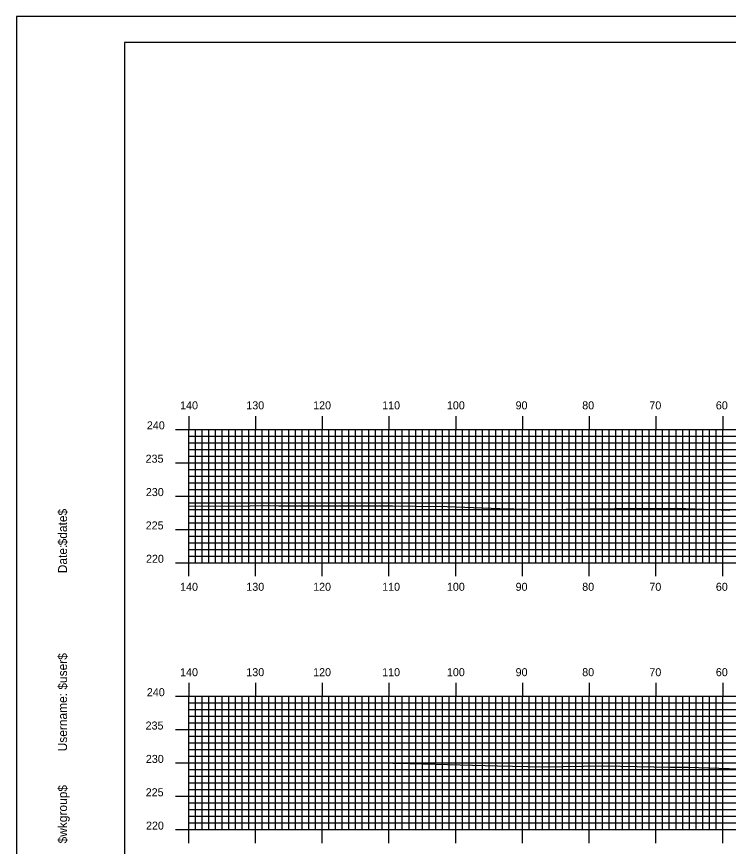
# Model space of a CAD drawing. Extents: x 1803503 to 1803847, y 442591 to 442811.
# Drawn here: x 1803503.4 to 1803610, y 442686.2 to 442810.5 of the extents above; entities that cross this region are included whole.
import ezdxf

# ---------------------------------------------------------------- set-up
doc = ezdxf.new("R2010")
doc.units = 0
for name, color, linetype in [('BORDER', 7, 'Continuous'), ('H_V ANNOTATION', 7, 'Continuous'), ('MAJOR', 7, 'Continuous'), ('MINOR', 7, 'Continuous'), ('PLOT BOUNDARY', 7, 'Continuous'), ('S_Roadway_Centerline', 7, 'Continuous')]:
    doc.layers.add(name, color=color, linetype=linetype)

msp = doc.modelspace()

# ---------------------------------------------------------------- linework, layer by layer
at = {"layer": 'BORDER'}
msp.add_lwpolyline([(1803519.54, 442596.67), (1803839.54, 442596.67), (1803839.54, 442806.67), (1803519.54, 442806.67)], close=True, dxfattribs=at)
at = {"layer": 'MAJOR'}
for p, q in [((1803529.14, 442750.67), (1803529.14, 442748.67)), ((1803539.14, 442750.67), (1803539.14, 442748.67)), ((1803549.14, 442750.67), (1803549.14, 442748.67)), ((1803559.14, 442750.67), (1803559.14, 442748.67)), ((1803569.14, 442750.67), (1803569.14, 442748.67)), ((1803579.14, 442750.67), (1803579.14, 442748.67)), ((1803589.14, 442750.67), (1803589.14, 442748.67)), ((1803599.14, 442750.67), (1803599.14, 442748.67)), ((1803609.14, 442750.67), (1803609.14, 442748.67)), ((1803527.14, 442748.67), (1803529.14, 442748.67)), ((1803529.14, 442748.67), (1803809.14, 442748.67)), ((1803529.14, 442728.67), (1803529.14, 442748.67)), ((1803529.14, 442728.67), (1803529.14, 442748.67)), ((1803529.14, 442748.67), (1803809.14, 442748.67)), ((1803539.14, 442728.67), (1803539.14, 442748.67)), ((1803549.14, 442728.67), (1803549.14, 442748.67)), ((1803559.14, 442728.67), (1803559.14, 442748.67)), ((1803569.14, 442728.67), (1803569.14, 442748.67)), ((1803579.14, 442728.67), (1803579.14, 442748.67)), ((1803589.14, 442728.67), (1803589.14, 442748.67)), ((1803599.14, 442728.67), (1803599.14, 442748.67)), ((1803609.14, 442728.67), (1803609.14, 442748.67)), ((1803527.14, 442743.67), (1803529.14, 442743.67)), ((1803529.14, 442743.67), (1803809.14, 442743.67)), ((1803527.14, 442738.67), (1803529.14, 442738.67)), ((1803529.14, 442738.67), (1803809.14, 442738.67)), ((1803527.14, 442733.67), (1803529.14, 442733.67)), ((1803529.14, 442733.67), (1803809.14, 442733.67)), ((1803527.14, 442728.67), (1803529.14, 442728.67)), ((1803529.14, 442728.67), (1803809.14, 442728.67)), ((1803529.14, 442728.67), (1803809.14, 442728.67)), ((1803529.14, 442726.66), (1803529.14, 442728.67)), ((1803539.14, 442726.66), (1803539.14, 442728.67)), ((1803549.14, 442726.66), (1803549.14, 442728.67)), ((1803559.14, 442726.66), (1803559.14, 442728.67)), ((1803569.14, 442726.66), (1803569.14, 442728.67)), ((1803579.14, 442726.66), (1803579.14, 442728.67)), ((1803589.14, 442726.66), (1803589.14, 442728.67)), ((1803599.14, 442726.66), (1803599.14, 442728.67)), ((1803609.14, 442726.66), (1803609.14, 442728.67)), ((1803529.14, 442710.67), (1803529.14, 442708.67)), ((1803539.14, 442710.67), (1803539.14, 442708.67)), ((1803549.14, 442710.67), (1803549.14, 442708.67)), ((1803559.14, 442710.67), (1803559.14, 442708.67)), ((1803569.14, 442710.67), (1803569.14, 442708.67)), ((1803579.14, 442710.67), (1803579.14, 442708.67)), ((1803589.14, 442710.67), (1803589.14, 442708.67)), ((1803599.14, 442710.67), (1803599.14, 442708.67)), ((1803609.14, 442710.67), (1803609.14, 442708.67)), ((1803527.14, 442708.67), (1803529.14, 442708.67)), ((1803529.14, 442708.67), (1803809.14, 442708.67)), ((1803529.14, 442688.67), (1803529.14, 442708.67)), ((1803529.14, 442688.67), (1803529.14, 442708.67)), ((1803529.14, 442708.67), (1803809.14, 442708.67)), ((1803539.14, 442688.67), (1803539.14, 442708.67)), ((1803549.14, 442688.67), (1803549.14, 442708.67)), ((1803559.14, 442688.67), (1803559.14, 442708.67)), ((1803569.14, 442688.67), (1803569.14, 442708.67)), ((1803579.14, 442688.67), (1803579.14, 442708.67)), ((1803589.14, 442688.67), (1803589.14, 442708.67)), ((1803599.14, 442688.67), (1803599.14, 442708.67)), ((1803609.14, 442688.67), (1803609.14, 442708.67)), ((1803527.14, 442703.67), (1803529.14, 442703.67)), ((1803529.14, 442703.67), (1803809.14, 442703.67)), ((1803527.14, 442698.67), (1803529.14, 442698.67)), ((1803529.14, 442698.67), (1803809.14, 442698.67)), ((1803527.14, 442693.67), (1803529.14, 442693.67)), ((1803529.14, 442693.67), (1803809.14, 442693.67)), ((1803527.14, 442688.67), (1803529.14, 442688.67)), ((1803529.14, 442688.67), (1803809.14, 442688.67)), ((1803529.14, 442688.67), (1803809.14, 442688.67)), ((1803529.14, 442686.66), (1803529.14, 442688.67)), ((1803539.14, 442686.66), (1803539.14, 442688.67)), ((1803549.14, 442686.66), (1803549.14, 442688.67)), ((1803559.14, 442686.66), (1803559.14, 442688.67)), ((1803569.14, 442686.66), (1803569.14, 442688.67)), ((1803579.14, 442686.66), (1803579.14, 442688.67)), ((1803589.14, 442686.66), (1803589.14, 442688.67)), ((1803599.14, 442686.66), (1803599.14, 442688.67)), ((1803609.14, 442686.66), (1803609.14, 442688.67))]:
    msp.add_line(p, q, dxfattribs=at)
at = {"layer": 'MINOR'}
for p, q in [((1803530.14, 442728.67), (1803530.14, 442748.67)), ((1803531.14, 442728.67), (1803531.14, 442748.67)), ((1803532.14, 442728.67), (1803532.14, 442748.67)), ((1803533.14, 442728.67), (1803533.14, 442748.67)), ((1803534.14, 442728.67), (1803534.14, 442748.67)), ((1803535.14, 442728.67), (1803535.14, 442748.67)), ((1803536.14, 442728.67), (1803536.14, 442748.67)), ((1803537.14, 442728.67), (1803537.14, 442748.67)), ((1803538.14, 442728.67), (1803538.14, 442748.67)), ((1803540.14, 442728.67), (1803540.14, 442748.67)), ((1803541.14, 442728.67), (1803541.14, 442748.67)), ((1803542.14, 442728.67), (1803542.14, 442748.67)), ((1803543.14, 442728.67), (1803543.14, 442748.67)), ((1803544.14, 442728.67), (1803544.14, 442748.67)), ((1803545.14, 442728.67), (1803545.14, 442748.67)), ((1803546.14, 442728.67), (1803546.14, 442748.67)), ((1803547.14, 442728.67), (1803547.14, 442748.67)), ((1803548.14, 442728.67), (1803548.14, 442748.67)), ((1803550.14, 442728.67), (1803550.14, 442748.67)), ((1803551.14, 442728.67), (1803551.14, 442748.67)), ((1803552.14, 442728.67), (1803552.14, 442748.67)), ((1803553.14, 442728.67), (1803553.14, 442748.67)), ((1803554.14, 442728.67), (1803554.14, 442748.67)), ((1803555.14, 442728.67), (1803555.14, 442748.67)), ((1803556.14, 442728.67), (1803556.14, 442748.67)), ((1803557.14, 442728.67), (1803557.14, 442748.67)), ((1803558.14, 442728.67), (1803558.14, 442748.67)), ((1803560.14, 442728.67), (1803560.14, 442748.67)), ((1803561.14, 442728.67), (1803561.14, 442748.67)), ((1803562.14, 442728.67), (1803562.14, 442748.67)), ((1803563.14, 442728.67), (1803563.14, 442748.67)), ((1803564.14, 442728.67), (1803564.14, 442748.67)), ((1803565.14, 442728.67), (1803565.14, 442748.67)), ((1803566.14, 442728.67), (1803566.14, 442748.67)), ((1803567.14, 442728.67), (1803567.14, 442748.67)), ((1803568.14, 442728.67), (1803568.14, 442748.67)), ((1803570.14, 442728.67), (1803570.14, 442748.67)), ((1803571.14, 442728.67), (1803571.14, 442748.67)), ((1803572.14, 442728.67), (1803572.14, 442748.67)), ((1803573.14, 442728.67), (1803573.14, 442748.67)), ((1803574.14, 442728.67), (1803574.14, 442748.67)), ((1803575.14, 442728.67), (1803575.14, 442748.67)), ((1803576.14, 442728.67), (1803576.14, 442748.67)), ((1803577.14, 442728.67), (1803577.14, 442748.67)), ((1803578.14, 442728.67), (1803578.14, 442748.67)), ((1803580.14, 442728.67), (1803580.14, 442748.67)), ((1803581.14, 442728.67), (1803581.14, 442748.67)), ((1803582.14, 442728.67), (1803582.14, 442748.67)), ((1803583.14, 442728.67), (1803583.14, 442748.67)), ((1803584.14, 442728.67), (1803584.14, 442748.67)), ((1803585.14, 442728.67), (1803585.14, 442748.67)), ((1803586.14, 442728.67), (1803586.14, 442748.67)), ((1803587.14, 442728.67), (1803587.14, 442748.67)), ((1803588.14, 442728.67), (1803588.14, 442748.67)), ((1803590.14, 442728.67), (1803590.14, 442748.67)), ((1803591.14, 442728.67), (1803591.14, 442748.67)), ((1803592.14, 442728.67), (1803592.14, 442748.67)), ((1803593.14, 442728.67), (1803593.14, 442748.67)), ((1803594.14, 442728.67), (1803594.14, 442748.67)), ((1803595.14, 442728.67), (1803595.14, 442748.67)), ((1803596.14, 442728.67), (1803596.14, 442748.67)), ((1803597.14, 442728.67), (1803597.14, 442748.67)), ((1803598.14, 442728.67), (1803598.14, 442748.67)), ((1803600.14, 442728.67), (1803600.14, 442748.67)), ((1803601.14, 442728.67), (1803601.14, 442748.67)), ((1803602.14, 442728.67), (1803602.14, 442748.67)), ((1803603.14, 442728.67), (1803603.14, 442748.67)), ((1803604.14, 442728.67), (1803604.14, 442748.67)), ((1803605.14, 442728.67), (1803605.14, 442748.67)), ((1803606.14, 442728.67), (1803606.14, 442748.67)), ((1803607.14, 442728.67), (1803607.14, 442748.67)), ((1803608.14, 442728.67), (1803608.14, 442748.67)), ((1803529.14, 442747.67), (1803809.14, 442747.67)), ((1803529.14, 442747.67), (1803531.14, 442747.67)), ((1803529.14, 442746.67), (1803809.14, 442746.67)), ((1803529.14, 442746.67), (1803531.14, 442746.67)), ((1803529.14, 442745.67), (1803809.14, 442745.67)), ((1803529.14, 442745.67), (1803531.14, 442745.67)), ((1803529.14, 442744.67), (1803809.14, 442744.67)), ((1803529.14, 442744.67), (1803531.14, 442744.67)), ((1803529.14, 442742.67), (1803809.14, 442742.67)), ((1803529.14, 442742.67), (1803531.14, 442742.67)), ((1803529.14, 442741.67), (1803809.14, 442741.67)), ((1803529.14, 442741.67), (1803531.14, 442741.67)), ((1803529.14, 442740.67), (1803809.14, 442740.67)), ((1803529.14, 442740.67), (1803531.14, 442740.67)), ((1803529.14, 442739.67), (1803809.14, 442739.67)), ((1803529.14, 442739.67), (1803531.14, 442739.67)), ((1803529.14, 442737.67), (1803809.14, 442737.67)), ((1803529.14, 442737.67), (1803531.14, 442737.67)), ((1803529.14, 442736.67), (1803809.14, 442736.67)), ((1803529.14, 442736.67), (1803531.14, 442736.67)), ((1803529.14, 442735.67), (1803809.14, 442735.67)), ((1803529.14, 442735.67), (1803531.14, 442735.67)), ((1803529.14, 442734.67), (1803809.14, 442734.67)), ((1803529.14, 442734.67), (1803531.14, 442734.67)), ((1803529.14, 442732.67), (1803809.14, 442732.67)), ((1803529.14, 442732.67), (1803531.14, 442732.67)), ((1803529.14, 442731.67), (1803809.14, 442731.67)), ((1803529.14, 442731.67), (1803531.14, 442731.67)), ((1803529.14, 442730.67), (1803809.14, 442730.67)), ((1803529.14, 442730.67), (1803531.14, 442730.67)), ((1803529.14, 442729.67), (1803809.14, 442729.67)), ((1803529.14, 442729.67), (1803531.14, 442729.67)), ((1803530.14, 442688.67), (1803530.14, 442708.67)), ((1803531.14, 442688.67), (1803531.14, 442708.67)), ((1803532.14, 442688.67), (1803532.14, 442708.67)), ((1803533.14, 442688.67), (1803533.14, 442708.67)), ((1803534.14, 442688.67), (1803534.14, 442708.67)), ((1803535.14, 442688.67), (1803535.14, 442708.67)), ((1803536.14, 442688.67), (1803536.14, 442708.67)), ((1803537.14, 442688.67), (1803537.14, 442708.67)), ((1803538.14, 442688.67), (1803538.14, 442708.67)), ((1803540.14, 442688.67), (1803540.14, 442708.67)), ((1803541.14, 442688.67), (1803541.14, 442708.67)), ((1803542.14, 442688.67), (1803542.14, 442708.67)), ((1803543.14, 442688.67), (1803543.14, 442708.67)), ((1803544.14, 442688.67), (1803544.14, 442708.67)), ((1803545.14, 442688.67), (1803545.14, 442708.67)), ((1803546.14, 442688.67), (1803546.14, 442708.67)), ((1803547.14, 442688.67), (1803547.14, 442708.67)), ((1803548.14, 442688.67), (1803548.14, 442708.67)), ((1803550.14, 442688.67), (1803550.14, 442708.67)), ((1803551.14, 442688.67), (1803551.14, 442708.67)), ((1803552.14, 442688.67), (1803552.14, 442708.67)), ((1803553.14, 442688.67), (1803553.14, 442708.67)), ((1803554.14, 442688.67), (1803554.14, 442708.67)), ((1803555.14, 442688.67), (1803555.14, 442708.67)), ((1803556.14, 442688.67), (1803556.14, 442708.67)), ((1803557.14, 442688.67), (1803557.14, 442708.67)), ((1803558.14, 442688.67), (1803558.14, 442708.67)), ((1803560.14, 442688.67), (1803560.14, 442708.67)), ((1803561.14, 442688.67), (1803561.14, 442708.67)), ((1803562.14, 442688.67), (1803562.14, 442708.67)), ((1803563.14, 442688.67), (1803563.14, 442708.67)), ((1803564.14, 442688.67), (1803564.14, 442708.67)), ((1803565.14, 442688.67), (1803565.14, 442708.67)), ((1803566.14, 442688.67), (1803566.14, 442708.67)), ((1803567.14, 442688.67), (1803567.14, 442708.67)), ((1803568.14, 442688.67), (1803568.14, 442708.67)), ((1803570.14, 442688.67), (1803570.14, 442708.67)), ((1803571.14, 442688.67), (1803571.14, 442708.67)), ((1803572.14, 442688.67), (1803572.14, 442708.67)), ((1803573.14, 442688.67), (1803573.14, 442708.67)), ((1803574.14, 442688.67), (1803574.14, 442708.67)), ((1803575.14, 442688.67), (1803575.14, 442708.67)), ((1803576.14, 442688.67), (1803576.14, 442708.67)), ((1803577.14, 442688.67), (1803577.14, 442708.67)), ((1803578.14, 442688.67), (1803578.14, 442708.67)), ((1803580.14, 442688.67), (1803580.14, 442708.67)), ((1803581.14, 442688.67), (1803581.14, 442708.67)), ((1803582.14, 442688.67), (1803582.14, 442708.67)), ((1803583.14, 442688.67), (1803583.14, 442708.67)), ((1803584.14, 442688.67), (1803584.14, 442708.67)), ((1803585.14, 442688.67), (1803585.14, 442708.67)), ((1803586.14, 442688.67), (1803586.14, 442708.67)), ((1803587.14, 442688.67), (1803587.14, 442708.67)), ((1803588.14, 442688.67), (1803588.14, 442708.67)), ((1803590.14, 442688.67), (1803590.14, 442708.67)), ((1803591.14, 442688.67), (1803591.14, 442708.67)), ((1803592.14, 442688.67), (1803592.14, 442708.67)), ((1803593.14, 442688.67), (1803593.14, 442708.67)), ((1803594.14, 442688.67), (1803594.14, 442708.67)), ((1803595.14, 442688.67), (1803595.14, 442708.67)), ((1803596.14, 442688.67), (1803596.14, 442708.67)), ((1803597.14, 442688.67), (1803597.14, 442708.67)), ((1803598.14, 442688.67), (1803598.14, 442708.67)), ((1803600.14, 442688.67), (1803600.14, 442708.67)), ((1803601.14, 442688.67), (1803601.14, 442708.67)), ((1803602.14, 442688.67), (1803602.14, 442708.67)), ((1803603.14, 442688.67), (1803603.14, 442708.67)), ((1803604.14, 442688.67), (1803604.14, 442708.67)), ((1803605.14, 442688.67), (1803605.14, 442708.67)), ((1803606.14, 442688.67), (1803606.14, 442708.67)), ((1803607.14, 442688.67), (1803607.14, 442708.67)), ((1803608.14, 442688.67), (1803608.14, 442708.67)), ((1803529.14, 442707.67), (1803809.14, 442707.67)), ((1803529.14, 442707.67), (1803531.14, 442707.67)), ((1803529.14, 442706.67), (1803809.14, 442706.67)), ((1803529.14, 442706.67), (1803531.14, 442706.67)), ((1803529.14, 442705.67), (1803809.14, 442705.67)), ((1803529.14, 442705.67), (1803531.14, 442705.67)), ((1803529.14, 442704.67), (1803809.14, 442704.67)), ((1803529.14, 442704.67), (1803531.14, 442704.67)), ((1803529.14, 442702.67), (1803809.14, 442702.67)), ((1803529.14, 442702.67), (1803531.14, 442702.67)), ((1803529.14, 442701.67), (1803809.14, 442701.67)), ((1803529.14, 442701.67), (1803531.14, 442701.67)), ((1803529.14, 442700.67), (1803809.14, 442700.67)), ((1803529.14, 442700.67), (1803531.14, 442700.67)), ((1803529.14, 442699.67), (1803809.14, 442699.67)), ((1803529.14, 442699.67), (1803531.14, 442699.67)), ((1803529.14, 442697.67), (1803809.14, 442697.67)), ((1803529.14, 442697.67), (1803531.14, 442697.67)), ((1803529.14, 442696.67), (1803809.14, 442696.67)), ((1803529.14, 442696.67), (1803531.14, 442696.67)), ((1803529.14, 442695.67), (1803809.14, 442695.67)), ((1803529.14, 442695.67), (1803531.14, 442695.67)), ((1803529.14, 442694.67), (1803809.14, 442694.67)), ((1803529.14, 442694.67), (1803531.14, 442694.67)), ((1803529.14, 442692.67), (1803809.14, 442692.67)), ((1803529.14, 442692.67), (1803531.14, 442692.67)), ((1803529.14, 442691.67), (1803809.14, 442691.67)), ((1803529.14, 442691.67), (1803531.14, 442691.67)), ((1803529.14, 442690.67), (1803809.14, 442690.67)), ((1803529.14, 442690.67), (1803531.14, 442690.67)), ((1803529.14, 442689.67), (1803809.14, 442689.67)), ((1803529.14, 442689.67), (1803531.14, 442689.67))]:
    msp.add_line(p, q, dxfattribs=at)
at = {"layer": 'PLOT BOUNDARY'}
msp.add_lwpolyline([(1803503.35, 442590.55), (1803843.35, 442590.55), (1803843.35, 442810.55), (1803503.35, 442810.55)], close=True, dxfattribs=at)
at = {"layer": 'S_Roadway_Centerline'}
for points in [[(1803529.14, 442737.18), (1803538.35, 442737.21), (1803540.31, 442737.27), (1803542.6, 442737.22), (1803552.62, 442737.22), (1803559.65, 442737.22), (1803563.19, 442737.17), (1803567.87, 442737.11), (1803575.74, 442736.83), (1803581.97, 442736.67), (1803592.91, 442736.82), (1803602.33, 442736.84), (1803610.21, 442736.54)], [(1803529.14, 442698.69), (1803541.02, 442698.65), (1803544.17, 442698.66), (1803548.96, 442698.7), (1803557.09, 442698.68), (1803562.32, 442698.58), (1803575.38, 442698.23), (1803582.17, 442698.09), (1803591.35, 442698.24), (1803601.34, 442698.03), (1803602.78, 442698.04), (1803603.95, 442698.02), (1803617.75, 442697.56)]]:
    msp.add_lwpolyline(points, dxfattribs=at)

# ---------------------------------------------------------------- texts
at = {"layer": 'BORDER'}
for s, p in [('$date$', (1803510.91, 442731.28)), ('Date:', (1803510.91, 442727.1)), ('$user$', (1803510.91, 442709.65)), ('Username:', (1803510.91, 442700.4)), ('$wkgroup$', (1803510.91, 442686.6))]:
    msp.add_text(s, height=1.339, rotation=90, dxfattribs=at).set_placement(p)
at = {"layer": 'H_V ANNOTATION'}
for s, p in [('140', (1803527.85, 442751.67)), ('130', (1803537.77, 442751.67)), ('120', (1803547.78, 442751.67)), ('110', (1803558.12, 442751.67)), ('100', (1803567.82, 442751.67)), ('90', (1803578.11, 442751.67)), ('80', (1803588.09, 442751.67)), ('70', (1803598.15, 442751.67)), ('60', (1803608.11, 442751.67)), ('240', (1803522.87, 442748.67)), ('235', (1803522.68, 442743.67)), ('230', (1803522.72, 442738.67)), ('225', (1803522.7, 442733.67)), ('220', (1803522.74, 442728.67)), ('140', (1803527.85, 442724.47)), ('130', (1803537.77, 442724.47)), ('120', (1803547.78, 442724.47)), ('110', (1803558.12, 442724.47)), ('100', (1803567.82, 442724.47)), ('90', (1803578.11, 442724.47)), ('80', (1803588.09, 442724.47)), ('70', (1803598.15, 442724.47)), ('60', (1803608.11, 442724.47)), ('140', (1803527.85, 442711.67)), ('130', (1803537.77, 442711.67)), ('120', (1803547.78, 442711.67)), ('110', (1803558.12, 442711.67)), ('100', (1803567.82, 442711.67)), ('90', (1803578.11, 442711.67)), ('80', (1803588.09, 442711.67)), ('70', (1803598.15, 442711.67)), ('60', (1803608.11, 442711.67)), ('240', (1803522.87, 442708.67)), ('235', (1803522.68, 442703.67)), ('230', (1803522.72, 442698.67)), ('225', (1803522.7, 442693.67)), ('220', (1803522.74, 442688.67))]:
    msp.add_text(s, height=1.2, dxfattribs=at).set_placement(p)
at = {"layer": 'MAJOR'}
for p in [(1803529.13, 442728.67), (1803529.13, 442688.67)]:
    msp.add_text('-', height=0.012, dxfattribs=at).set_placement(p)

doc.saveas('drawing.dxf')
